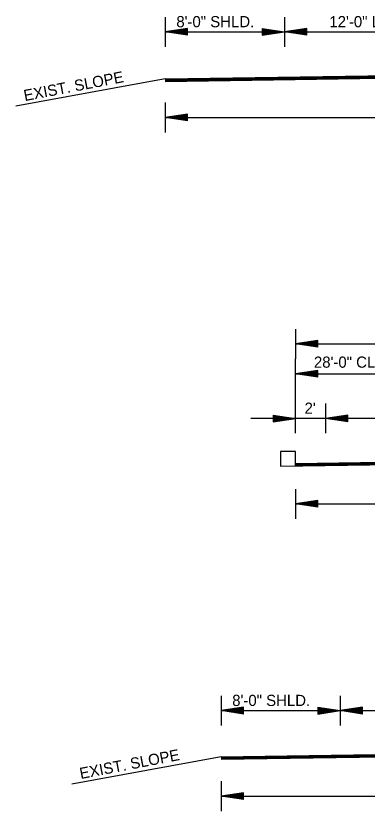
# Model space of a CAD drawing. Extents: x 550980 to 1930787, y -1972975 to 596640.
# Drawn here: x 551066 to 551302, y -1961450 to -1960917 of the extents above; entities that cross this region are included whole.
import ezdxf

# ---------------------------------------------------------------- set-up
doc = ezdxf.new("R2010")
doc.units = 0
doc.layers.add('R_Border', color=7, linetype='Continuous')
doc.layers.add('R_Draft', color=7, linetype='Continuous')

msp = doc.modelspace()

# ---------------------------------------------------------------- linework, layer by layer
at = {"layer": 'R_Border'}
msp.add_lwpolyline([(551253.84, -1961218.44), (551253.84, -1961209.01), (551243.67, -1961209.01), (551243.67, -1961218.8)], dxfattribs=at)
at = {"layer": 'R_Draft'}
for p, q in [((551166.34, -1960917.33), (551166.34, -1960937.33)), ((551246.34, -1960917.33), (551246.34, -1960937.33)), ((551181.34, -1960925.08), (551166.34, -1960927.33)), ((551166.34, -1960927.33), (551921.34, -1960927.33)), ((551181.34, -1960929.58), (551166.34, -1960927.33)), ((551181.34, -1960925.46), (551168.84, -1960927.33)), ((551181.34, -1960929.21), (551168.84, -1960927.33)), ((551181.34, -1960925.84), (551171.42, -1960927.33)), ((551181.34, -1960928.83), (551171.42, -1960927.33)), ((551181.34, -1960926.22), (551173.92, -1960927.33)), ((551181.34, -1960928.45), (551173.92, -1960927.33)), ((551181.34, -1960926.6), (551176.46, -1960927.33)), ((551181.34, -1960928.06), (551176.46, -1960927.33)), ((551181.34, -1960926.98), (551178.97, -1960927.33)), ((551181.34, -1960927.69), (551178.97, -1960927.33)), ((551181.34, -1960929.58), (551181.34, -1960925.08)), ((551231.34, -1960925.08), (551246.34, -1960927.33)), ((551231.34, -1960925.08), (551231.34, -1960929.58)), ((551231.34, -1960925.46), (551243.83, -1960927.33)), ((551231.34, -1960925.84), (551241.25, -1960927.33)), ((551231.34, -1960926.22), (551238.76, -1960927.33)), ((551231.34, -1960926.61), (551236.21, -1960927.33)), ((551231.34, -1960926.98), (551233.71, -1960927.33)), ((551231.34, -1960929.58), (551246.34, -1960927.33)), ((551231.34, -1960928.07), (551236.21, -1960927.33)), ((551231.34, -1960928.83), (551241.25, -1960927.33)), ((551231.34, -1960929.21), (551243.83, -1960927.33)), ((551231.34, -1960928.45), (551238.76, -1960927.33)), ((551231.34, -1960927.69), (551233.71, -1960927.33)), ((551261.34, -1960925.08), (551246.34, -1960927.33)), ((551261.34, -1960929.58), (551246.34, -1960927.33)), ((551261.34, -1960925.46), (551248.84, -1960927.33)), ((551261.34, -1960929.21), (551248.84, -1960927.33)), ((551261.34, -1960925.84), (551251.42, -1960927.33)), ((551261.34, -1960928.83), (551251.42, -1960927.33)), ((551261.34, -1960926.22), (551253.92, -1960927.33)), ((551261.34, -1960928.45), (551253.92, -1960927.33)), ((551261.34, -1960926.6), (551256.46, -1960927.33)), ((551261.34, -1960928.06), (551256.46, -1960927.33)), ((551261.34, -1960926.98), (551258.97, -1960927.33)), ((551261.34, -1960927.69), (551258.97, -1960927.33)), ((551261.34, -1960929.58), (551261.34, -1960925.08)), ((551166.34, -1960958.83), (551066.27, -1960977.2)), ((551166.34, -1960974.74), (551166.34, -1960994.74)), ((551181.34, -1960982.49), (551166.34, -1960984.74)), ((551166.34, -1960984.74), (551921.34, -1960984.74)), ((551181.34, -1960986.99), (551166.34, -1960984.74)), ((551181.34, -1960982.87), (551168.84, -1960984.74)), ((551181.34, -1960986.62), (551168.84, -1960984.74)), ((551181.34, -1960983.25), (551171.42, -1960984.74)), ((551181.34, -1960986.24), (551171.42, -1960984.74)), ((551181.34, -1960983.63), (551173.92, -1960984.74)), ((551181.34, -1960985.86), (551173.92, -1960984.74)), ((551181.34, -1960984.01), (551176.46, -1960984.74)), ((551181.34, -1960985.47), (551176.46, -1960984.74)), ((551181.34, -1960984.39), (551178.97, -1960984.74)), ((551181.34, -1960985.1), (551178.97, -1960984.74)), ((551181.34, -1960986.99), (551181.34, -1960982.49)), ((551253.84, -1961126.76), (551253.84, -1961146.76)), ((551268.84, -1961134.51), (551253.84, -1961136.76)), ((551268.84, -1961134.89), (551256.34, -1961136.76)), ((551268.84, -1961135.27), (551258.92, -1961136.76)), ((551268.84, -1961135.65), (551261.42, -1961136.76)), ((551268.84, -1961136.03), (551263.96, -1961136.76)), ((551268.84, -1961136.41), (551266.47, -1961136.76)), ((551268.84, -1961139.01), (551268.84, -1961134.51)), ((551253.84, -1961136.76), (551833.84, -1961136.76)), ((551268.84, -1961139.01), (551253.84, -1961136.76)), ((551268.84, -1961138.64), (551256.34, -1961136.76)), ((551268.84, -1961138.26), (551258.92, -1961136.76)), ((551268.84, -1961137.88), (551261.42, -1961136.76)), ((551268.84, -1961137.49), (551263.96, -1961136.76)), ((551268.84, -1961137.12), (551266.47, -1961136.76)), ((551253.84, -1961196.76), (551253.84, -1961146.76)), ((551268.84, -1961154.51), (551253.84, -1961156.76)), ((551253.84, -1961156.76), (551533.84, -1961156.76)), ((551268.84, -1961159.01), (551253.84, -1961156.76)), ((551268.84, -1961154.89), (551256.34, -1961156.76)), ((551268.84, -1961158.64), (551256.34, -1961156.76)), ((551268.84, -1961155.27), (551258.92, -1961156.76)), ((551268.84, -1961158.26), (551258.92, -1961156.76)), ((551268.84, -1961155.65), (551261.42, -1961156.76)), ((551268.84, -1961157.88), (551261.42, -1961156.76)), ((551268.84, -1961156.03), (551263.96, -1961156.76)), ((551268.84, -1961157.49), (551263.96, -1961156.76)), ((551268.84, -1961156.41), (551266.47, -1961156.76)), ((551268.84, -1961157.12), (551266.47, -1961156.76)), ((551268.84, -1961159.01), (551268.84, -1961154.51)), ((551273.84, -1961176.76), (551273.84, -1961196.76)), ((551238.84, -1961184.51), (551253.84, -1961186.76)), ((551238.84, -1961184.51), (551238.84, -1961189.01)), ((551288.84, -1961184.51), (551273.84, -1961186.76)), ((551288.84, -1961189.01), (551288.84, -1961184.51)), ((551533.84, -1961186.76), (551223.84, -1961186.76)), ((551238.84, -1961184.89), (551251.33, -1961186.76)), ((551238.84, -1961185.27), (551248.75, -1961186.76)), ((551238.84, -1961185.65), (551246.26, -1961186.76)), ((551238.84, -1961186.04), (551243.71, -1961186.76)), ((551238.84, -1961186.41), (551241.21, -1961186.76)), ((551238.84, -1961189.01), (551253.84, -1961186.76)), ((551238.84, -1961187.5), (551243.71, -1961186.76)), ((551238.84, -1961188.26), (551248.75, -1961186.76)), ((551238.84, -1961188.64), (551251.33, -1961186.76)), ((551238.84, -1961187.88), (551246.26, -1961186.76)), ((551238.84, -1961187.12), (551241.21, -1961186.76)), ((551288.84, -1961189.01), (551273.84, -1961186.76)), ((551288.84, -1961184.89), (551276.34, -1961186.76)), ((551288.84, -1961188.64), (551276.34, -1961186.76)), ((551288.84, -1961185.27), (551278.92, -1961186.76)), ((551288.84, -1961188.26), (551278.92, -1961186.76)), ((551288.84, -1961185.65), (551281.42, -1961186.76)), ((551288.84, -1961187.88), (551281.42, -1961186.76)), ((551288.84, -1961186.03), (551283.96, -1961186.76)), ((551288.84, -1961187.49), (551283.96, -1961186.76)), ((551288.84, -1961186.41), (551286.47, -1961186.76)), ((551288.84, -1961187.12), (551286.47, -1961186.76)), ((551253.84, -1961234.17), (551253.84, -1961254.17)), ((551268.84, -1961241.92), (551253.84, -1961244.17)), ((551268.84, -1961242.3), (551256.34, -1961244.17)), ((551268.84, -1961242.68), (551258.92, -1961244.17)), ((551268.84, -1961243.06), (551261.42, -1961244.17)), ((551268.84, -1961243.44), (551263.96, -1961244.17)), ((551268.84, -1961246.42), (551268.84, -1961241.92)), ((551253.84, -1961244.17), (551833.84, -1961244.17)), ((551268.84, -1961246.42), (551253.84, -1961244.17)), ((551268.84, -1961246.05), (551256.34, -1961244.17)), ((551268.84, -1961245.67), (551258.92, -1961244.17)), ((551268.84, -1961245.29), (551261.42, -1961244.17)), ((551268.84, -1961244.9), (551263.96, -1961244.17)), ((551268.84, -1961243.82), (551266.47, -1961244.17)), ((551268.84, -1961244.53), (551266.47, -1961244.17)), ((551203.84, -1961372.91), (551203.84, -1961392.91)), ((551283.84, -1961372.91), (551283.84, -1961392.91)), ((551218.84, -1961380.66), (551203.84, -1961382.91)), ((551218.84, -1961381.04), (551206.34, -1961382.91)), ((551218.84, -1961381.42), (551208.92, -1961382.91)), ((551218.84, -1961381.79), (551211.42, -1961382.91)), ((551218.84, -1961382.18), (551213.96, -1961382.91)), ((551218.84, -1961385.16), (551218.84, -1961380.66)), ((551268.84, -1961380.66), (551283.84, -1961382.91)), ((551268.84, -1961380.66), (551268.84, -1961385.16)), ((551268.84, -1961381.04), (551281.33, -1961382.91)), ((551268.84, -1961381.42), (551278.75, -1961382.91)), ((551268.84, -1961381.79), (551276.26, -1961382.91)), ((551268.84, -1961382.18), (551273.71, -1961382.91)), ((551298.84, -1961380.66), (551283.84, -1961382.91)), ((551298.84, -1961381.04), (551286.34, -1961382.91)), ((551298.84, -1961381.42), (551288.92, -1961382.91)), ((551298.84, -1961381.79), (551291.42, -1961382.91)), ((551298.84, -1961382.18), (551293.96, -1961382.91)), ((551298.84, -1961385.16), (551298.84, -1961380.66)), ((551203.84, -1961382.91), (551883.84, -1961382.91)), ((551218.84, -1961385.16), (551203.84, -1961382.91)), ((551218.84, -1961384.79), (551206.34, -1961382.91)), ((551218.84, -1961384.4), (551208.92, -1961382.91)), ((551218.84, -1961384.03), (551211.42, -1961382.91)), ((551218.84, -1961383.64), (551213.96, -1961382.91)), ((551218.84, -1961382.56), (551216.47, -1961382.91)), ((551218.84, -1961383.26), (551216.47, -1961382.91)), ((551268.84, -1961382.56), (551271.21, -1961382.91)), ((551268.84, -1961385.16), (551283.84, -1961382.91)), ((551268.84, -1961383.65), (551273.71, -1961382.91)), ((551268.84, -1961384.4), (551278.75, -1961382.91)), ((551268.84, -1961384.79), (551281.33, -1961382.91)), ((551268.84, -1961384.03), (551276.26, -1961382.91)), ((551268.84, -1961383.26), (551271.21, -1961382.91)), ((551298.84, -1961385.16), (551283.84, -1961382.91)), ((551298.84, -1961384.79), (551286.34, -1961382.91)), ((551298.84, -1961384.4), (551288.92, -1961382.91)), ((551298.84, -1961384.03), (551291.42, -1961382.91)), ((551298.84, -1961383.64), (551293.96, -1961382.91)), ((551298.84, -1961382.56), (551296.47, -1961382.91)), ((551298.84, -1961383.26), (551296.47, -1961382.91)), ((551203.84, -1961413.84), (551103.77, -1961432.22)), ((551203.84, -1961430.32), (551203.84, -1961450.32)), ((551218.84, -1961438.07), (551203.84, -1961440.32)), ((551203.84, -1961440.32), (551883.84, -1961440.32)), ((551218.84, -1961442.57), (551203.84, -1961440.32)), ((551218.84, -1961438.45), (551206.34, -1961440.32)), ((551218.84, -1961442.2), (551206.34, -1961440.32)), ((551218.84, -1961438.83), (551208.92, -1961440.32)), ((551218.84, -1961441.82), (551208.92, -1961440.32)), ((551218.84, -1961439.21), (551211.42, -1961440.32)), ((551218.84, -1961441.44), (551211.42, -1961440.32)), ((551218.84, -1961439.59), (551213.96, -1961440.32)), ((551218.84, -1961441.05), (551213.96, -1961440.32)), ((551218.84, -1961439.97), (551216.47, -1961440.32)), ((551218.84, -1961440.68), (551216.47, -1961440.32)), ((551218.84, -1961442.57), (551218.84, -1961438.07))]:
    msp.add_line(p, q, dxfattribs=at)
for points in [[(551166.34, -1960958.83), (551543.84, -1960953.16), (551921.34, -1960958.83)], [(551166.34, -1960959.13), (551543.84, -1960953.46), (551921.34, -1960959.13)], [(551166.34, -1960959.43), (551543.84, -1960953.76), (551921.34, -1960959.43)], [(551166.34, -1960959.73), (551543.84, -1960954.06), (551921.34, -1960959.73)], [(551166.34, -1960960.03), (551543.84, -1960954.36), (551921.34, -1960960.03)], [(551166.34, -1960960.33), (551543.84, -1960954.66), (551921.34, -1960960.33)], [(551166.34, -1960960.53), (551543.84, -1960954.86), (551921.34, -1960960.53)], [(551243.67, -1961218.8), (551543.84, -1961214.29), (551844.01, -1961218.8)], [(551253.84, -1961216.94), (551543.84, -1961212.59), (551833.84, -1961216.94)], [(551253.84, -1961217.24), (551543.84, -1961212.89), (551833.84, -1961217.24)], [(551253.84, -1961217.54), (551543.84, -1961213.19), (551833.84, -1961217.54)], [(551253.84, -1961217.84), (551543.84, -1961213.49), (551833.84, -1961217.84)], [(551253.84, -1961218.14), (551543.84, -1961213.79), (551833.84, -1961218.14)], [(551253.84, -1961218.44), (551543.84, -1961214.09), (551833.84, -1961218.44)], [(551203.84, -1961413.84), (551543.84, -1961408.74), (551883.84, -1961413.84)], [(551203.84, -1961414.14), (551543.84, -1961409.04), (551883.84, -1961414.14)], [(551203.84, -1961414.44), (551543.84, -1961409.34), (551883.84, -1961414.44)], [(551203.84, -1961414.74), (551543.84, -1961409.64), (551883.84, -1961414.74)], [(551203.84, -1961415.04), (551543.84, -1961409.94), (551883.84, -1961415.04)], [(551203.84, -1961415.34), (551543.84, -1961410.24), (551883.84, -1961415.34)], [(551203.84, -1961415.54), (551543.84, -1961410.44), (551883.84, -1961415.54)]]:
    msp.add_lwpolyline(points, dxfattribs=at)

# ---------------------------------------------------------------- texts
at = {"layer": 'R_Border'}
msp.add_text('28\'-0" CLEAR ROADWAY (POLYMER OVERLAY)', height=7.5, dxfattribs=at).set_placement((551266.16, -1961152.73))
at = {"layer": 'R_Draft'}
for s, p in [('8\'-0" SHLD.', (551173.86, -1960924.2)), ('12\'-0" LANE', (551276.54, -1960924.2)), ("2'", (551259.88, -1961183.63)), ('8\'-0" SHLD.', (551211.36, -1961379.78))]:
    msp.add_text(s, height=7.5, dxfattribs=at).set_placement(p)
for p in [(551072.25, -1960973.82), (551109.75, -1961428.84)]:
    msp.add_text('EXIST. SLOPE', height=7.5, rotation=10.8829, dxfattribs=at).set_placement(p)

doc.saveas('drawing.dxf')
